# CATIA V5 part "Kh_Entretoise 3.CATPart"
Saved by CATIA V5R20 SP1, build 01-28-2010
Part number: Entretoise 3
Bounding box of the stored display mesh (mm): x 0 to 34, y -10.5 to 10.5, z -10.5 to 10.5
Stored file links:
  G:\Khaled_CFAO_2011\SIL\SIL_GR1\tmerino\Khaled\CAD_Thinkmotion\Kh_Entretoise 3.CATPart
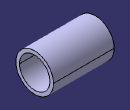
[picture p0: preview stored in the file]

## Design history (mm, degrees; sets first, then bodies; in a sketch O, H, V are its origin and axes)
Body1 (main body)
  Sketch1 on yz-plane, origin (0, 0, 0), H (0, 1, 0), V (0, 0, 1)
    circle A1 centre (0, 0) radius 8.5
    circle A2 centre (0, 0) radius 10.5
    radius A1 = 8.5
    radius A2 = 10.5
  Pad1: profile Sketch1, direction (1, 0, 0), length 34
